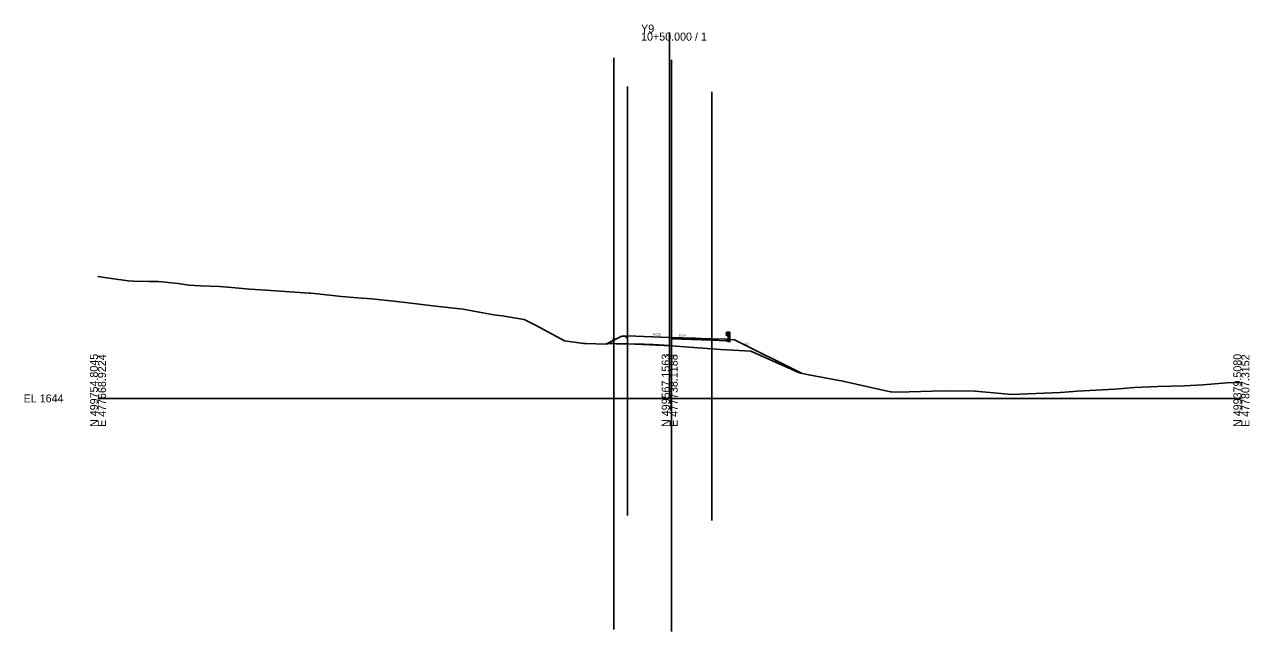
# Model space of a CAD drawing. Extents: x -26 to 403, y -99 to 4540.
# Drawn here: x -25.7 to 402.8, y 418.4 to 630.8 of the extents above; entities that cross this region are included whole.
import ezdxf

# ---------------------------------------------------------------- set-up
doc = ezdxf.new("R2010")
doc.units = 0
for name, color, linetype in [('Exist Cross Section Cell', 7, 'Continuous'), ('Exist XS Center Line Elevation Label', 7, 'Continuous'), ('Exist XS Ground Line', 7, 'Continuous'), ('Prop XS Dump Level', 7, 'Continuous'), ('Prop XS Earthwork Shape', 7, 'Continuous'), ('Prop XS EOT Tick Mark', 7, 'Continuous'), ('Prop XS Finish Grade', 7, 'Continuous'), ('Prop XS Finish Grade Earthwork', 7, 'Continuous'), ('Prop XS Finish Grade Paved Shoulder', 7, 'Continuous'), ('Prop XS Finish Grade Pavement', 7, 'Continuous'), ('Prop XS Guardrail', 7, 'Continuous'), ('Prop XS Hydro Fill Slope Data', 7, 'Continuous'), ('Prop XS Pvmt Edge Slope', 7, 'Continuous'), ('Prop XS SE Text', 7, 'Continuous'), ('Prop XS Shoulder Borrow Shape', 7, 'Continuous'), ('Prop XS Side Slope Text', 7, 'Continuous'), ('Prop XS Subgrade Earthwork', 7, 'Continuous'), ('Scratch_Level_1', 7, 'Continuous'), ('Scratch_Level_6', 7, 'Continuous')]:
    doc.layers.add(name, color=color, linetype=linetype)

msp = doc.modelspace()

# ---------------------------------------------------------------- linework, layer by layer
at = {"layer": 'Exist Cross Section Cell'}
for p, q in [((200, 500), (200, 627.98)), ((0, 500), (200, 500)), ((200, 500), (400, 500))]:
    msp.add_line(p, q, dxfattribs=at)
at = {"layer": 'Exist XS Ground Line'}
msp.add_lwpolyline([(0, 542.66), (4.69, 541.98), (10.53, 541.17), (12.48, 541.06), (17.77, 540.91), (20.27, 540.9), (21.19, 540.88), (28.06, 540.21), (31.85, 539.64), (35.85, 539.33), (42.51, 539.2), (46.68, 538.84), (53.17, 538.22), (56.96, 537.96), (63.83, 537.5), (73.85, 536.85), (74.49, 536.81), (75.59, 536.7), (85.15, 535.67), (90.74, 535.22), (95.81, 534.78), (104.5, 533.94), (106.47, 533.7), (107.63, 533.56), (117.13, 532.34), (124.51, 531.53), (127.79, 531.18), (133.41, 530.2), (138.45, 529.29), (141.4, 528.91), (149.11, 527.6), (153.32, 525.48), (163.25, 520.09), (169.09, 519.37), (169.9, 519.23), (170.69, 519.21), (177.7, 518.97), (179.04, 519.2), (180.46, 519.15), (181.33, 519.14), (190.92, 518.98), (194.26, 518.82), (200, 518.48), (200.68, 518.44), (217.76, 517.06), (228.42, 516.53), (242.51, 510.22), (244.05, 509.56), (245.08, 509.02), (245.88, 508.84), (248.63, 508.22), (260.59, 505.97), (275.57, 502.69), (276.76, 502.44), (277.22, 502.35), (277.62, 502.3), (279.59, 502.17), (296.19, 502.61), (306.9, 502.48), (319.65, 501.36), (336.55, 502.07), (339.75, 502.29), (342.51, 502.58), (355.7, 503.27), (362.58, 503.8), (370.75, 504.12), (380.09, 504.43), (386.49, 504.78), (394.91, 505.48), (400, 505.51)], dxfattribs=at)
at = {"layer": 'Prop XS Dump Level'}
for p, q in [((200, 521.36), (191, 521.65)), ((209, 521.07), (200, 521.36))]:
    msp.add_line(p, q, dxfattribs=at)
at = {"layer": 'Prop XS Earthwork Shape'}
for points in [[(185.3, 521.29), (184.78, 521.3), (184.28, 521.8), (183.3, 521.77), (177.7, 518.97), (179.04, 519.2), (180.46, 519.15), (181.33, 519.14), (185.3, 519.07)], [(214.7, 520.35), (219.71, 520.18), (220.27, 520.17), (220.75, 520.64), (222.71, 520.49), (246.12, 508.78), (245.88, 508.84), (245.08, 509.02), (244.05, 509.56), (242.51, 510.22), (228.42, 516.53), (217.76, 517.06), (200.68, 518.44), (200.68, 520.79)]]:
    msp.add_lwpolyline(points, close=True, dxfattribs=at)
at = {"layer": 'Prop XS EOT Tick Mark'}
for p, q in [((185.3, 521.83), (185.3, 522.83)), ((214.7, 520.89), (214.7, 521.89))]:
    msp.add_line(p, q, dxfattribs=at)
at = {"layer": 'Prop XS Finish Grade'}
for p, q in [((185.3, 521.83), (184.28, 521.8)), ((219.71, 520.73), (220.75, 520.64))]:
    msp.add_line(p, q, dxfattribs=at)
at = {"layer": 'Prop XS Finish Grade Earthwork'}
for p, q in [((183.3, 521.77), (177.7, 518.97)), ((184.28, 521.8), (183.3, 521.77)), ((220.75, 520.64), (222.71, 520.49)), ((222.71, 520.49), (246.12, 508.78))]:
    msp.add_line(p, q, dxfattribs=at)
at = {"layer": 'Prop XS Finish Grade Paved Shoulder'}
msp.add_line((214.7, 520.89), (219.71, 520.73), dxfattribs=at)
at = {"layer": 'Prop XS Finish Grade Pavement'}
for p, q in [((185.3, 521.83), (200, 521.36)), ((200, 521.36), (214.7, 520.89))]:
    msp.add_line(p, q, dxfattribs=at)
at = {"layer": 'Prop XS Guardrail'}
for p, q in [((220.03, 523.15), (219.74, 522.94)), ((220.03, 522.61), (219.74, 522.82)), ((220.52, 523.15), (220.03, 523.15)), ((220.03, 523.15), (220.03, 521.99)), ((220.52, 523.15), (220.52, 520.66)), ((220.52, 523.15), (221.02, 523.15)), ((221.02, 523.15), (221.02, 520.66)), ((220.03, 522.52), (219.74, 522.32)), ((220.03, 521.99), (219.74, 522.19)), ((220.03, 522.57), (220.03, 522.61)), ((220.03, 522.57), (220.03, 522.52)), ((220.52, 521.99), (220.03, 521.99)), ((220.52, 520.66), (221.02, 520.66)), ((220.52, 520.66), (220.52, 519.65)), ((221.02, 520.66), (221.02, 519.65))]:
    msp.add_line(p, q, dxfattribs=at)
for centre, start, end in [((219.78, 522.88), 125.003, 235.0112), ((219.78, 522.25), 125.0059, 235.0366)]:
    msp.add_arc(centre, 0.0776, start, end, dxfattribs=at)
at = {"layer": 'Prop XS Hydro Fill Slope Data'}
msp.add_line((183.3, 521.77), (178.28, 519.26), dxfattribs=at)
at = {"layer": 'Prop XS Pvmt Edge Slope'}
for p, q in [((185.3, 521.83), (184.78, 521.3)), ((219.71, 520.73), (220.27, 520.17))]:
    msp.add_line(p, q, dxfattribs=at)
at = {"layer": 'Prop XS Shoulder Borrow Shape'}
for points in [[(185.3, 521.83), (184.78, 521.3), (184.28, 521.8)], [(220.27, 520.17), (220.75, 520.64), (219.71, 520.73)]]:
    msp.add_lwpolyline(points, close=True, dxfattribs=at)
at = {"layer": 'Prop XS Subgrade Earthwork'}
for p, q in [((184.78, 521.3), (184.28, 521.8)), ((185.3, 521.29), (184.78, 521.3)), ((185.3, 521.29), (185.3, 519.07)), ((214.7, 520.35), (200.68, 520.79)), ((200.68, 520.79), (200.68, 518.44)), ((214.7, 520.35), (219.71, 520.18)), ((219.71, 520.18), (220.27, 520.17)), ((220.27, 520.17), (220.75, 520.64))]:
    msp.add_line(p, q, dxfattribs=at)
at = {"layer": 'Scratch_Level_1'}
for p, q in [((180.46, 619.15), (180.46, 419.15)), ((200.68, 618.44), (200.68, 418.44))]:
    msp.add_line(p, q, dxfattribs=at)
at = {"layer": 'Scratch_Level_6'}
for p, q in [((185.3, 609.07), (185.3, 459.07)), ((214.7, 607.31), (214.7, 457.31)), ((185.3, 519.07), (200.68, 518.44))]:
    msp.add_line(p, q, dxfattribs=at)

# ---------------------------------------------------------------- texts
at = {"layer": 'Exist Cross Section Cell'}
for s, p in [('Y9', (190, 627.98)), ('10+50.000 / 1', (190, 625.18)), ('EL 1644', (-26, 498.6))]:
    msp.add_text(s, height=2.8, dxfattribs=at).set_placement(p)
for s, p in [('N 499754.8045', (0, 490)), ('E 477668.9224', (2.8, 490)), ('N 499567.1563', (200, 490)), ('E 477738.1188', (202.8, 490)), ('N 499379.5080', (400, 490)), ('E 477807.3152', (402.8, 490))]:
    msp.add_text(s, height=2.8, rotation=90, dxfattribs=at).set_placement(p)
at = {"layer": 'Exist XS Center Line Elevation Label'}
msp.add_text('1662.48', height=0.9, dxfattribs=at).set_placement((197.9, 514.58))
at = {"layer": 'Prop XS Dump Level'}
for p in [(183.3, 521.73), (221.92, 520.47)]:
    msp.add_text('Case1', height=0.04, dxfattribs=at).set_placement(p)
at = {"layer": 'Prop XS SE Text'}
for p in [(194.22, 522.04), (203.22, 521.75)]:
    msp.add_text('0.032', height=0.75, rotation=358.1672, dxfattribs=at).set_placement(p)
at = {"layer": 'Prop XS Side Slope Text'}
for rotation, p in [(26.5651, (179.78, 520.43)), (333.4349, (226.2, 519.11))]:
    msp.add_text('2:1', height=0.75, rotation=rotation, dxfattribs=at).set_placement(p)

doc.saveas('drawing.dxf')
